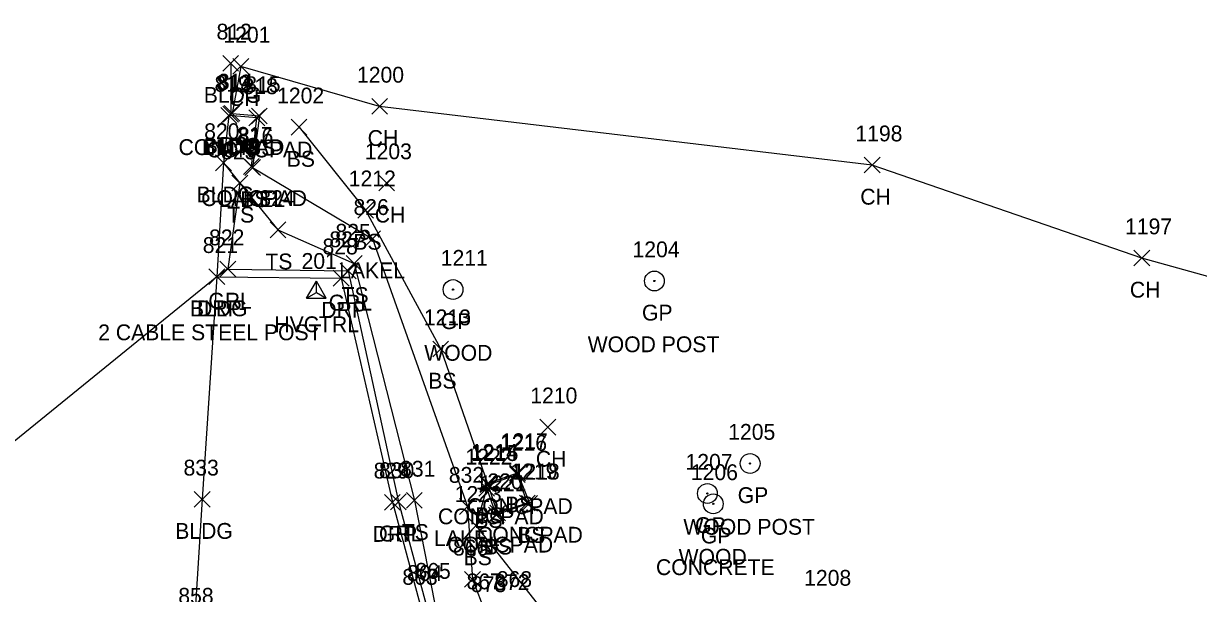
# Model space of a CAD drawing. Extents: x 1716490 to 1717645, y 888034 to 890004.
# Drawn here: x 1716763.9 to 1716912.5, y 888279.7 to 888351.8 of the extents above; entities that cross this region are included whole.
import ezdxf

# ---------------------------------------------------------------- set-up
doc = ezdxf.new("R2010")
doc.units = 0
for name, color, linetype in [('C_A', 7, 'Continuous'), ('C_I', 7, 'Continuous'), ('CPSM', 7, 'Continuous'), ('L_A', 7, 'Continuous'), ('L_I', 7, 'Continuous'), ('L_TIC', 7, 'Continuous'), ('LAWE', 7, 'Continuous'), ('LBC', 7, 'Continuous'), ('LELB', 7, 'Continuous'), ('LS', 7, 'Continuous'), ('LSOGP', 7, 'Continuous'), ('R_A', 7, 'Continuous'), ('R_C', 7, 'Continuous'), ('R_I', 7, 'Continuous'), ('R_TIC', 7, 'Continuous'), ('RDP', 7, 'Continuous'), ('RGP', 7, 'Continuous'), ('RGR', 7, 'Continuous'), ('U_I', 7, 'Continuous')]:
    doc.layers.add(name, color=color, linetype=linetype)

msp = doc.modelspace()

# ---------------------------------------------------------------- linework, layer by layer
at = {"layer": 'CPSM'}
for p, q in [((1716799.72, 888317.05), (1716800.97, 888319.21)), ((1716799.72, 888317.05), (1716800.97, 888319.21)), ((1716802.22, 888317.05), (1716800.97, 888319.21)), ((1716800.97, 888317.77), (1716800.97, 888319.21)), ((1716802.22, 888317.05), (1716800.97, 888319.21)), ((1716800.97, 888317.77), (1716800.97, 888319.21)), ((1716799.72, 888317.05), (1716800.97, 888317.77)), ((1716799.72, 888317.05), (1716800.97, 888317.77)), ((1716799.72, 888317.05), (1716802.22, 888317.05)), ((1716799.72, 888317.05), (1716802.22, 888317.05)), ((1716800.97, 888317.77), (1716800.97, 888317.77)), ((1716800.97, 888317.77), (1716802.22, 888317.05)), ((1716800.97, 888317.77), (1716800.97, 888317.77)), ((1716800.97, 888317.77), (1716802.22, 888317.05))]:
    msp.add_line(p, q, dxfattribs=at)
at = {"layer": 'L_TIC'}
for points in [[(1716789.15, 888345.76), (1716791.15, 888347.76)], [(1716791.15, 888345.76), (1716789.15, 888347.76)], [(1716790.42, 888345.37), (1716792.42, 888347.37)], [(1716792.42, 888345.37), (1716790.42, 888347.37)], [(1716807.97, 888340.31), (1716809.97, 888342.31)], [(1716809.97, 888340.31), (1716807.97, 888342.31)], [(1716788.91, 888339.16), (1716790.91, 888341.16)], [(1716790.91, 888339.16), (1716788.91, 888341.16)], [(1716788.91, 888339.16), (1716790.91, 888341.16)], [(1716790.91, 888339.16), (1716788.91, 888341.16)], [(1716789.15, 888339.32), (1716791.15, 888341.32)], [(1716791.15, 888339.32), (1716789.15, 888341.32)], [(1716789.31, 888339.43), (1716791.31, 888341.43)], [(1716791.31, 888339.43), (1716789.31, 888341.43)], [(1716792.44, 888338.86), (1716794.44, 888340.86)], [(1716794.44, 888338.86), (1716792.44, 888340.86)], [(1716792.77, 888339.1), (1716794.77, 888341.1)], [(1716794.77, 888339.1), (1716792.77, 888341.1)], [(1716797.78, 888337.68), (1716799.78, 888339.68)], [(1716799.78, 888337.68), (1716797.78, 888339.68)], [(1716788.24, 888333.17), (1716790.24, 888335.17)], [(1716790.24, 888333.17), (1716788.24, 888335.17)], [(1716791.76, 888332.71), (1716793.76, 888334.71)], [(1716793.76, 888332.71), (1716791.76, 888334.71)], [(1716791.92, 888332.59), (1716793.92, 888334.59)], [(1716793.92, 888332.59), (1716791.92, 888334.59)], [(1716791.92, 888332.59), (1716793.92, 888334.59)], [(1716793.92, 888332.59), (1716791.92, 888334.59)], [(1716870.25, 888332.89), (1716872.25, 888334.89)], [(1716872.25, 888332.89), (1716870.25, 888334.89)], [(1716790.29, 888330.62), (1716792.29, 888332.62)], [(1716792.29, 888330.62), (1716790.29, 888332.62)], [(1716808.87, 888330.63), (1716810.87, 888332.63)], [(1716810.87, 888330.63), (1716808.87, 888332.63)], [(1716806.2, 888327.2), (1716808.2, 888329.2)], [(1716808.2, 888327.2), (1716806.2, 888329.2)], [(1716795.12, 888324.71), (1716797.12, 888326.71)], [(1716797.12, 888324.71), (1716795.12, 888326.71)], [(1716807.09, 888323.58), (1716809.09, 888325.58)], [(1716809.09, 888323.58), (1716807.09, 888325.58)], [(1716904.33, 888321.14), (1716906.33, 888323.14)], [(1716906.33, 888321.14), (1716904.33, 888323.14)], [(1716804.75, 888320.46), (1716806.75, 888322.46)], [(1716806.75, 888320.46), (1716804.75, 888322.46)], [(1716787.4, 888318.78), (1716789.4, 888320.78)], [(1716789.4, 888318.78), (1716787.4, 888320.78)], [(1716815.69, 888309.64), (1716817.69, 888311.64)], [(1716817.69, 888309.64), (1716815.69, 888311.64)], [(1716829.23, 888299.77), (1716831.23, 888301.77)], [(1716831.23, 888299.77), (1716829.23, 888301.77)], [(1716825.4, 888293.99), (1716827.4, 888295.99)], [(1716827.4, 888293.99), (1716825.4, 888295.99)], [(1716821.62, 888292.63), (1716823.62, 888294.63)], [(1716823.62, 888292.63), (1716821.62, 888294.63)], [(1716821.7, 888292.49), (1716823.7, 888294.49)], [(1716823.7, 888292.49), (1716821.7, 888294.49)], [(1716825.37, 888293.78), (1716827.37, 888295.78)], [(1716827.37, 888293.78), (1716825.37, 888295.78)], [(1716821.51, 888292.04), (1716823.51, 888294.04)], [(1716823.51, 888292.04), (1716821.51, 888294.04)], [(1716785.54, 888290.65), (1716787.54, 888292.65)], [(1716787.54, 888290.65), (1716785.54, 888292.65)], [(1716812.36, 888290.51), (1716814.36, 888292.51)], [(1716814.36, 888290.51), (1716812.36, 888292.51)], [(1716819.08, 888289.73), (1716821.08, 888291.73)], [(1716821.08, 888289.73), (1716819.08, 888291.73)], [(1716826.64, 888290.17), (1716828.64, 888292.17)], [(1716828.64, 888290.17), (1716826.64, 888292.17)], [(1716826.92, 888290.14), (1716828.92, 888292.14)], [(1716828.92, 888290.14), (1716826.92, 888292.14)], [(1716822.72, 888288.67), (1716824.72, 888290.67)], [(1716824.72, 888288.67), (1716822.72, 888290.67)], [(1716822.89, 888288.92), (1716824.89, 888290.92)], [(1716824.89, 888288.92), (1716822.89, 888290.92)], [(1716820.15, 888287.32), (1716822.15, 888289.32)], [(1716822.15, 888287.32), (1716820.15, 888289.32)], [(1716819.72, 888280.54), (1716821.72, 888282.54)], [(1716821.72, 888280.54), (1716819.72, 888282.54)]]:
    msp.add_lwpolyline(points, dxfattribs=at)
at = {"layer": 'LAWE'}
msp.add_lwpolyline([(1716792.92, 888333.59), (1716808.09, 888324.58), (1716820.08, 888290.73), (1716820.72, 888281.54), (1716822.37, 888277.27), (1716826.19, 888277.56), (1716826.5, 888273.88), (1716836.72, 888265.48), (1716850.62, 888258.77), (1716877.17, 888260.55), (1716881.32, 888255.9), (1716887.74, 888253.86), (1716893, 888253.31), (1716893.17, 888249.27), (1716879.79, 888244.82)], dxfattribs=at)
at = {"layer": 'LBC'}
msp.add_lwpolyline([(1716790.15, 888346.76), (1716790.15, 888340.32), (1716789.91, 888340.16), (1716789.24, 888334.17), (1716788.4, 888319.78), (1716786.54, 888291.65), (1716784, 888251.37), (1716721.34, 888252.74), (1716722.06, 888265.93)], dxfattribs=at)
at = {"layer": 'LELB'}
for points in [[(1716790.31, 888340.43), (1716793.77, 888340.1), (1716792.92, 888333.59)], [(1716798.78, 888338.68), (1716807.2, 888328.2), (1716816.69, 888310.64), (1716822.62, 888293.63), (1716826.4, 888294.99), (1716827.92, 888291.14), (1716823.72, 888289.67), (1716822.51, 888293.04), (1716821.15, 888288.32), (1716833.51, 888272.56), (1716850.99, 888261.91), (1716864.72, 888262.29), (1716881.12, 888261.05)], [(1716791.29, 888331.62), (1716796.12, 888325.71), (1716805.75, 888321.46), (1716813.36, 888291.51), (1716815.91, 888278.6), (1716830.76, 888256), (1716850.12, 888255.72), (1716867.76, 888258.31)]]:
    msp.add_lwpolyline(points, dxfattribs=at)
at = {"layer": 'LS'}
for points in [[(1716792.76, 888333.71), (1716793.44, 888339.86), (1716789.91, 888340.16)], [(1716822.7, 888293.49), (1716826.37, 888294.78), (1716827.64, 888291.17), (1716823.89, 888289.92)], [(1716823.89, 888289.92), (1716822.7, 888293.49)]]:
    msp.add_lwpolyline(points, dxfattribs=at)
at = {"layer": 'LSOGP'}
msp.add_lwpolyline([(1716927.78, 888315.88), (1716905.33, 888322.14), (1716871.24, 888333.89), (1716808.97, 888341.31), (1716791.42, 888346.37), (1716790.32, 888340.43), (1716790.15, 888340.32), (1716789.9, 888340.16), (1716789.24, 888334.17), (1716791.29, 888331.62), (1716789.78, 888320.76), (1716788.41, 888319.78), (1716722.06, 888265.93), (1716706.46, 888265.74), (1716676.19, 888281.45), (1716673.98, 888261.56), (1716673.31, 888255.8), (1716671.32, 888244.59), (1716669.08, 888220.6), (1716669.13, 888208.32), (1716669.38, 888192.85), (1716667.9, 888172.89)], dxfattribs=at)
at = {"layer": 'R_TIC'}
for points in [[(1716788.78, 888319.75), (1716790.78, 888321.75)], [(1716790.78, 888319.75), (1716788.78, 888321.75)], [(1716803.99, 888319.51), (1716805.99, 888321.51)], [(1716805.99, 888319.51), (1716803.99, 888321.51)], [(1716787.4, 888318.78), (1716789.4, 888320.78)], [(1716789.4, 888318.78), (1716787.4, 888320.78)], [(1716803.11, 888318.6), (1716805.11, 888320.6)], [(1716805.11, 888318.6), (1716803.11, 888320.6)], [(1716809.58, 888290.27), (1716811.58, 888292.27)], [(1716811.58, 888290.27), (1716809.58, 888292.27)], [(1716810.34, 888290.32), (1716812.34, 888292.32)], [(1716812.34, 888290.32), (1716810.34, 888292.32)]]:
    msp.add_lwpolyline(points, dxfattribs=at)
at = {"layer": 'RDP'}
msp.add_lwpolyline([(1716788.4, 888319.78), (1716804.11, 888319.6), (1716810.58, 888291.27), (1716814.24, 888277.84), (1716821.75, 888264.05), (1716831.12, 888244.39), (1716836.63, 888239.83)], dxfattribs=at)
at = {"layer": 'RGP'}
for p, q in [((1716843.71, 888319.24), (1716843.71, 888319.24)), ((1716818.26, 888318.16), (1716818.26, 888318.16)), ((1716855.81, 888296.17), (1716855.81, 888296.17)), ((1716850.41, 888292.38), (1716850.41, 888292.38)), ((1716851.15, 888291.07), (1716851.15, 888291.07))]:
    msp.add_line(p, q, dxfattribs=at)
for centre, radius in [((1716843.71, 888319.24), 1.25), ((1716818.26, 888318.16), 1.25), ((1716818.26, 888318.16), 0.0833), ((1716843.71, 888319.24), 0.0833), ((1716855.81, 888296.17), 1.25), ((1716855.81, 888296.17), 0.0833), ((1716850.41, 888292.38), 1.25), ((1716851.15, 888291.07), 1.25), ((1716850.41, 888292.38), 0.0833), ((1716851.15, 888291.07), 0.0833)]:
    msp.add_circle(centre, radius, dxfattribs=at)
at = {"layer": 'RGR'}
msp.add_lwpolyline([(1716789.78, 888320.75), (1716804.99, 888320.51), (1716811.34, 888291.32), (1716814.84, 888278.32), (1716822.47, 888264.47)], dxfattribs=at)

# ---------------------------------------------------------------- texts
at = {"layer": 'C_A'}
msp.add_text('HVCTRL', height=2, dxfattribs=at).set_placement((1716795.66, 888312.77))
msp.add_text('HVCTRL', height=2, dxfattribs=at).set_placement((1716795.66, 888312.77))
at = {"layer": 'C_I'}
msp.add_text('201', height=2, dxfattribs=at).set_placement((1716799.1, 888320.77))
msp.add_text('201', height=2, dxfattribs=at).set_placement((1716799.1, 888320.77))
at = {"layer": 'L_A'}
for s, p in [('BLDG', (1716786.74, 888341.76)), ('CH', (1716789.91, 888341.37)), ('CH', (1716807.46, 888336.31)), ('CONCPAD', (1716783.55, 888335.16)), ('BLDG', (1716786.5, 888335.16)), ('BLDG', (1716786.74, 888335.32)), ('CONCPAD', (1716787.09, 888334.86)), ('BS', (1716788.76, 888335.43)), ('BS', (1716792.21, 888335.1)), ('BS', (1716797.23, 888333.68)), ('BLDG', (1716785.83, 888329.17)), ('CONCPAD', (1716786.41, 888328.71)), ('LAKEL', (1716788.69, 888328.59)), ('BS', (1716791.36, 888328.59)), ('CH', (1716869.74, 888328.89)), ('TS', (1716789.7, 888326.62)), ('CH', (1716808.36, 888326.63)), ('BS', (1716805.64, 888323.2)), ('TS', (1716794.53, 888320.71)), ('LAKEL', (1716803.85, 888319.58)), ('TS', (1716804.16, 888316.46)), ('CH', (1716903.82, 888317.14)), ('BLDG', (1716784.99, 888314.78)), ('BS', (1716815.13, 888305.64)), ('CH', (1716828.72, 888295.77)), ('CONCPAD', (1716820.01, 888289.78)), ('BS', (1716824.84, 888289.99)), ('CONCPAD', (1716816.35, 888288.49)), ('BS', (1716820.95, 888288.04)), ('BS', (1716821.06, 888288.63)), ('BLDG', (1716783.13, 888286.65)), ('TS', (1716811.77, 888286.51)), ('LAKEL', (1716815.84, 888285.73)), ('CONCPAD', (1716821.29, 888286.17)), ('BS', (1716826.36, 888286.14)), ('CONCPAD', (1716817.53, 888284.92)), ('BS', (1716822.16, 888284.67)), ('BS', (1716819.59, 888283.32))]:
    msp.add_text(s, height=2, dxfattribs=at).set_placement(p)
at = {"layer": 'L_I'}
for s, p in [('812', (1716788.35, 888349.76)), ('1201', (1716789.22, 888349.37)), ('819', (1716788.1, 888343.16)), ('819', (1716788.1, 888343.16)), ('813', (1716788.35, 888343.32)), ('814', (1716788.52, 888343.43)), ('815', (1716791.98, 888343.1)), ('1200', (1716806.11, 888344.31)), ('818', (1716791.64, 888342.86)), ('1202', (1716796.01, 888341.68)), ('820', (1716786.79, 888337.17)), ('817', (1716790.97, 888336.71)), ('816', (1716791.07, 888336.59)), ('816', (1716791.07, 888336.59)), ('1198', (1716869.12, 888336.89)), ('823', (1716788.93, 888334.62)), ('1203', (1716807.1, 888334.63)), ('1212', (1716805.07, 888331.2)), ('824', (1716793.76, 888328.71)), ('826', (1716805.67, 888327.58)), ('1197', (1716903.21, 888325.14)), ('825', (1716803.39, 888324.46)), ('821', (1716786.61, 888322.78)), ('1213', (1716814.56, 888313.64)), ('1210', (1716828.02, 888303.77)), ('1216', (1716824.19, 888297.78)), ('1217', (1716824.28, 888297.99)), ('1222', (1716819.82, 888296.04)), ('1214', (1716820.5, 888296.63)), ('1215', (1716820.57, 888296.49)), ('833', (1716784.18, 888294.65)), ('831', (1716811.56, 888294.51)), ('1219', (1716825.51, 888294.17)), ('1218', (1716825.79, 888294.14)), ('832', (1716817.72, 888293.73)), ('1220', (1716821.11, 888292.92)), ('1221', (1716821.59, 888292.67)), ('1223', (1716818.46, 888291.32)), ('866', (1716818.25, 888284.54)), ('865', (1716813.5, 888281.6)), ('868', (1716823.78, 888280.56)), ('867', (1716819.96, 888280.27)), ('867', (1716819.96, 888280.27)), ('873', (1716820.52, 888279.91)), ('872', (1716823.46, 888280.17))]:
    msp.add_text(s, height=2, dxfattribs=at).set_placement(p)
at = {"layer": 'R_A'}
for s, p in [('DRP', (1716785.89, 888314.78)), ('GRL', (1716787.32, 888315.75)), ('GRL', (1716802.53, 888315.51)), ('DRP', (1716801.6, 888314.6)), ('GP', (1716842.14, 888314.24)), ('GP', (1716816.69, 888313.16)), ('GP', (1716854.24, 888291.17)), ('GP', (1716848.85, 888287.38)), ('DRP', (1716808.07, 888286.27)), ('GRL', (1716808.88, 888286.32)), ('GP', (1716849.58, 888286.07))]:
    msp.add_text(s, height=2, dxfattribs=at).set_placement(p)
at = {"layer": 'R_C'}
for s, p in [('2 CABLE STEEL POST', (1716773.39, 888311.75)), ('WOOD', (1716814.61, 888309.16)), ('WOOD POST', (1716835.28, 888310.24)), ('WOOD POST', (1716847.37, 888287.17)), ('CONCRETE', (1716843.91, 888282.07)), ('WOOD', (1716846.77, 888283.38))]:
    msp.add_text(s, height=2, dxfattribs=at).set_placement(p)
at = {"layer": 'R_I'}
for s, p in [('822', (1716787.41, 888323.75)), ('821', (1716786.61, 888322.78)), ('828', (1716801.75, 888322.6)), ('827', (1716802.62, 888323.51)), ('1204', (1716840.94, 888322.24)), ('1211', (1716816.7, 888321.16)), ('1205', (1716853.04, 888299.17)), ('829', (1716808.21, 888294.27)), ('830', (1716808.89, 888294.32)), ('1207', (1716847.64, 888295.38)), ('1206', (1716848.32, 888294.07)), ('863', (1716811.84, 888280.84)), ('864', (1716812.43, 888281.32)), ('1208', (1716862.64, 888280.72))]:
    msp.add_text(s, height=2, dxfattribs=at).set_placement(p)
at = {"layer": 'U_I'}
msp.add_text('858', height=2, dxfattribs=at).set_placement((1716783.52, 888278.45))

doc.saveas('drawing.dxf')
